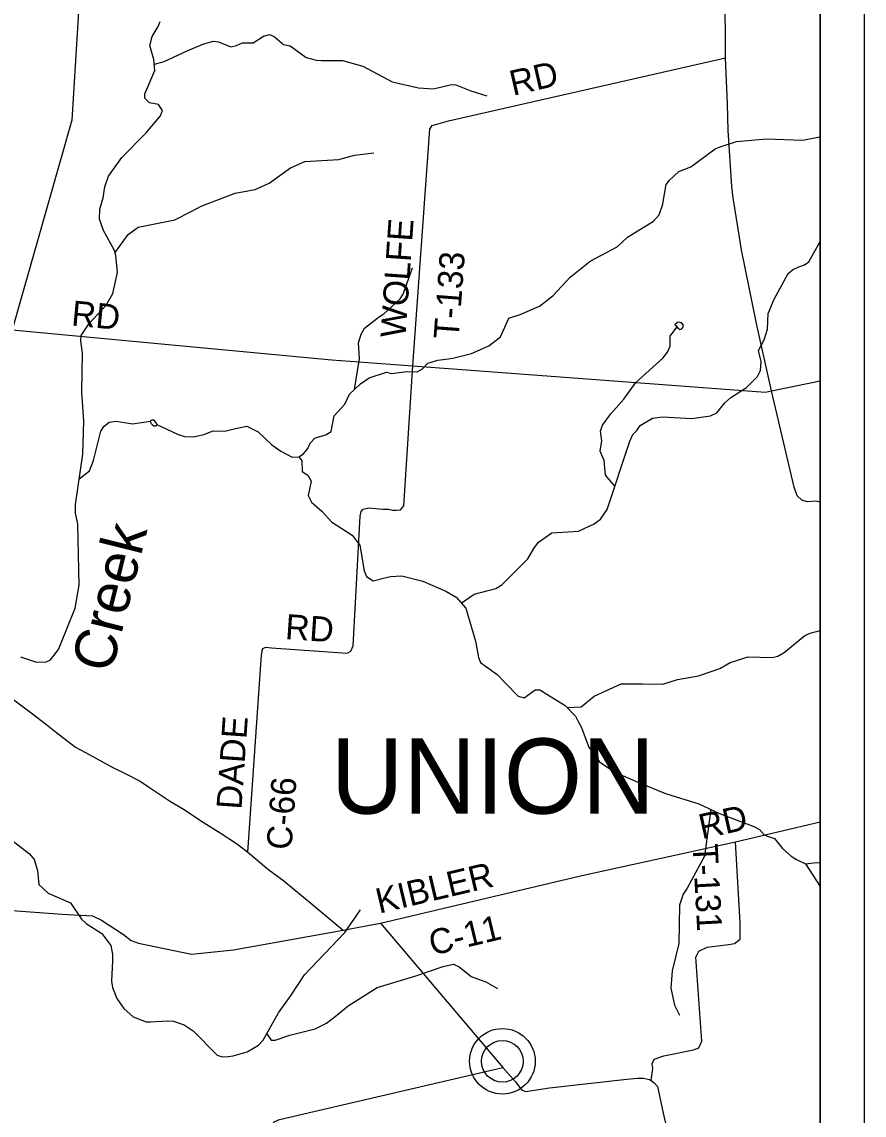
# Model space of a CAD drawing. Extents: x 0 to 48.6, y 0 to 22.
# Drawn here: x 7.09 to 9, y 14.998 to 17.478 of the extents above; entities that cross this region are included whole.
import ezdxf

# ---------------------------------------------------------------- set-up
doc = ezdxf.new("R2010")
doc.units = 0
for name, color, linetype in [('GM_X_Corporation', 7, 'Continuous'), ('GM_X_County_Road', 7, 'Continuous'), ('GM_X_County_Road_Text', 7, 'Continuous'), ('GM_X_County_Text', 7, 'Continuous'), ('GM_X_Minor_Lake', 7, 'Continuous'), ('GM_X_Minor_River', 7, 'Continuous'), ('GM_X_Minor_River_Text', 7, 'Continuous'), ('GM_X_State_Route', 7, 'Continuous'), ('GM_X_Township_Road', 7, 'Continuous'), ('GM_X_Township_Road_Text', 7, 'Continuous'), ('GM_X_Township_Text', 7, 'Continuous'), ('GM_X_Unincorporated', 7, 'Continuous'), ('GM_X_Unincorporated_Location', 7, 'Continuous'), ('SH_Data', 7, 'Continuous')]:
    doc.layers.add(name, color=color, linetype=linetype)

msp = doc.modelspace()

# ---------------------------------------------------------------- linework, layer by layer
at = {"layer": 'GM_X_Corporation'}
msp.add_lwpolyline([(5.0944, 14.1), (8.9, 14.1), (8.9, 19.5692), (8.5348, 19.2897), (7.2261, 18.2847), (6.9471, 18.0777), (6.5365, 17.7727), (5.8387, 17.2541), (5.5264, 17.0064), (4.6225, 16.3345), (4.044, 15.9033), (4.0346, 15.8959), (4.0398, 15.887), (4.3544, 15.3539), (4.4679, 15.1616), (4.7542, 14.6766)], close=True, dxfattribs=at)
at = {"layer": 'GM_X_County_Road'}
msp.add_line((8.7903, 16.6409), (8.9, 16.664), dxfattribs=at)
for points in [[(8.7903, 16.6409), (8.756, 16.7936), (8.7217, 16.9604), (8.7133, 17.013), (8.7028, 17.0786), (8.6997, 17.1041), (8.6913, 17.2315), (8.6903, 17.2915), (8.6855, 17.3963), (8.6851, 17.5535), (8.6814, 17.7601)], [(7.0193, 17.5612), (7.1388, 17.5717), (7.1722, 17.5746), (7.1927, 17.5752), (7.2079, 17.5751), (7.2192, 17.5729), (7.2224, 17.563), (7.2032, 17.2545), (7.0677, 16.7791)], [(6.9605, 15.9949), (6.9706, 16.0404), (6.9818, 16.3461), (6.9871, 16.4731), (6.9936, 16.5052), (7.0677, 16.7791), (7.7928, 16.7109), (7.9765, 16.6977), (8.7761, 16.6379), (8.7903, 16.6409)], [(7.6023, 15.5947), (7.6318, 16.0202), (7.6335, 16.0403), (7.634, 16.046), (7.6349, 16.0513), (7.6366, 16.0565), (7.6431, 16.0598), (7.6563, 16.0583), (7.8279, 16.0458), (7.836, 16.0505), (7.8409, 16.0629), (7.8574, 16.357), (7.8596, 16.3672), (7.8639, 16.3728), (7.8757, 16.3759), (7.9083, 16.3727), (7.9212, 16.3724), (7.9314, 16.3706), (7.9397, 16.37), (7.9488, 16.3713), (7.9559, 16.3798), (7.9765, 16.6977)], [(8.9, 16.3883), (8.8914, 16.3908), (8.8709, 16.3894), (8.8588, 16.3931), (8.8481, 16.4029), (8.841, 16.4228), (8.7903, 16.6409)], [(7.9035, 15.4333), (8.357, 15.5406), (8.7081, 15.6183), (8.9, 15.6634)], [(6.7885, 15.4828), (7.1812, 15.4537), (7.2502, 15.4504), (7.2704, 15.4404), (7.32, 15.4076), (7.3378, 15.3942), (7.3544, 15.388), (7.4748, 15.3636), (7.5699, 15.3732), (7.8187, 15.418)], [(7.8187, 15.418), (7.8658, 15.4267), (7.9035, 15.4333)]]:
    msp.add_lwpolyline(points, dxfattribs=at)
at = {"layer": 'GM_X_Minor_Lake'}
for points in [[(8.5765, 16.7846), (8.5817, 16.7804), (8.5863, 16.7818), (8.589, 16.7845), (8.5902, 16.7901), (8.5861, 16.7955), (8.5804, 16.7967), (8.577, 16.7956), (8.5705, 16.7908)], [(8.5705, 16.7908), (8.5729, 16.7889), (8.5765, 16.7846)], [(7.3964, 16.5645), (7.3953, 16.5679), (7.3912, 16.5725), (7.3882, 16.5744), (7.3856, 16.5745), (7.3825, 16.5734), (7.381, 16.5715), (7.3832, 16.5669), (7.3851, 16.5643), (7.3888, 16.5619), (7.3941, 16.5615)], [(7.3941, 16.5615), (7.3964, 16.5645)]]:
    msp.add_lwpolyline(points, dxfattribs=at)
at = {"layer": 'GM_X_Minor_River'}
for points in [[(7.0866, 16.0375), (7.1232, 16.0256), (7.1452, 16.0264), (7.1548, 16.0312), (7.1726, 16.054), (7.2109, 16.1482), (7.2197, 16.2001), (7.2165, 16.3389), (7.2112, 16.3633), (7.2112, 16.3834), (7.2285, 16.4973), (7.2305, 16.572), (7.2262, 16.638), (7.2272, 16.7264), (7.2235, 16.7541), (7.2244, 16.7666), (7.2423, 16.794), (7.2809, 16.8355), (7.2965, 16.8615), (7.3067, 16.9095), (7.3032, 16.9482), (7.2999, 16.9593), (7.2752, 17.0048), (7.2658, 17.03), (7.2669, 17.0527), (7.2745, 17.0788), (7.2779, 17.1034), (7.2867, 17.1275), (7.3169, 17.1699), (7.372, 17.2259), (7.4045, 17.2649), (7.4088, 17.2769), (7.3999, 17.2903), (7.3791, 17.2941), (7.3691, 17.3045), (7.3688, 17.3143), (7.3917, 17.3671), (7.3894, 17.3921), (7.3801, 17.4245), (7.3857, 17.4445), (7.3986, 17.4675), (7.4033, 17.4784)], [(7.3904, 17.3818), (7.4129, 17.3876), (7.466, 17.413), (7.5022, 17.4283), (7.5243, 17.4337), (7.5357, 17.4327), (7.5635, 17.4213), (7.5769, 17.4241), (7.5906, 17.43), (7.6145, 17.43), (7.6379, 17.4455), (7.6512, 17.4491), (7.6621, 17.4444), (7.6831, 17.4266), (7.6986, 17.4234), (7.7349, 17.397), (7.7576, 17.391), (7.7693, 17.3904), (7.8167, 17.39), (7.8631, 17.3776), (7.9297, 17.3416), (7.989, 17.3282), (8.0235, 17.3261), (8.0642, 17.3357), (8.074, 17.3352), (8.1083, 17.3214), (8.1442, 17.3098)], [(7.3963, 16.5648), (7.4431, 16.5425), (7.4589, 16.5373), (7.479, 16.5366), (7.5026, 16.5416), (7.5236, 16.55), (7.5505, 16.5492), (7.5741, 16.5552), (7.6, 16.5605), (7.6256, 16.5476), (7.6566, 16.5187), (7.6768, 16.5039), (7.7032, 16.4906), (7.718, 16.4915), (7.7283, 16.4978), (7.7383, 16.5098), (7.7438, 16.5222), (7.755, 16.5346), (7.779, 16.541), (7.7913, 16.5488), (7.7983, 16.5844), (7.8222, 16.6109), (7.8328, 16.6331), (7.8575, 16.657), (7.8774, 16.6704), (7.9166, 16.683), (7.9291, 16.6805), (7.9622, 16.685), (7.986, 16.6842), (7.9987, 16.6912), (8.0106, 16.7036), (8.0335, 16.7104), (8.0574, 16.7134), (8.0669, 16.7148), (8.1099, 16.7255), (8.1489, 16.7431), (8.175, 16.7636), (8.1942, 16.8054), (8.2198, 16.8137), (8.264, 16.8327), (8.2944, 16.8573), (8.3333, 16.8988), (8.379, 16.9349), (8.4398, 16.9677), (8.4633, 16.9897), (8.5226, 17.0259), (8.535, 17.0398), (8.5433, 17.0643), (8.545, 17.0745), (8.5512, 17.1086), (8.5586, 17.1191), (8.5798, 17.1385), (8.6072, 17.1487), (8.6621, 17.1899), (8.6732, 17.1947), (8.7109, 17.2066), (8.7785, 17.2128), (8.8599, 17.2092), (8.9, 17.2173)], [(7.3013, 16.9544), (7.3308, 16.9956), (7.3538, 17.0119), (7.4371, 17.0284), (7.4754, 17.0483), (7.4968, 17.0601), (7.5735, 17.0889), (7.6187, 17.0977), (7.6504, 17.1123), (7.6991, 17.1465), (7.7319, 17.1611), (7.8086, 17.1653), (7.8193, 17.1689), (7.8444, 17.1757), (7.8881, 17.1811)], [(8.0863, 16.1597), (8.1157, 16.18), (8.1648, 16.1925), (8.1782, 16.2007), (8.2372, 16.2601), (8.2512, 16.2834), (8.2617, 16.298), (8.2916, 16.3188), (8.3523, 16.3228), (8.3874, 16.3393), (8.402, 16.3497), (8.4171, 16.3718), (8.4685, 16.5269), (8.4756, 16.5416), (8.4844, 16.5513), (8.4918, 16.5626), (8.5198, 16.5788), (8.5429, 16.5823), (8.6096, 16.5782), (8.6514, 16.584), (8.6663, 16.591), (8.6841, 16.6138), (8.6979, 16.6261), (8.7332, 16.6487), (8.7582, 16.6737), (8.7653, 16.6873), (8.7663, 16.7074), (8.7607, 16.7325), (8.7736, 16.7569), (8.7811, 16.7807), (8.7825, 16.8167), (8.7959, 16.8491), (8.8275, 16.9071), (8.8375, 16.9156), (8.8516, 16.9219), (8.865, 16.927), (8.8746, 16.9336), (8.9, 16.9799)], [(7.8444, 16.6443), (7.8553, 16.7143), (7.8532, 16.7496), (7.8592, 16.7696), (7.867, 16.7828), (7.9008, 16.8096), (7.9108, 16.8155), (7.9477, 16.8498), (7.9547, 16.8603), (7.9754, 16.9199)], [(8.4346, 16.4246), (8.4138, 16.45), (8.4106, 16.483), (8.4014, 16.504), (8.4048, 16.5279), (8.4021, 16.5495), (8.4069, 16.5627), (8.4259, 16.589), (8.4552, 16.6223), (8.4824, 16.6598), (8.5435, 16.7154), (8.5543, 16.7285), (8.5599, 16.742), (8.5602, 16.7652), (8.5756, 16.7856)], [(7.22, 16.4412), (7.2431, 16.4595), (7.2526, 16.4829), (7.2688, 16.5494), (7.2758, 16.5603), (7.2881, 16.5699), (7.304, 16.572), (7.3411, 16.5661), (7.3815, 16.5721)], [(7.718, 16.4915), (7.725, 16.482), (7.7254, 16.4581), (7.7381, 16.4499), (7.7459, 16.4361), (7.7393, 16.4032), (7.7467, 16.3883), (7.771, 16.3675), (7.7926, 16.3432), (7.8023, 16.337), (7.8391, 16.3137), (7.8566, 16.2906), (7.8663, 16.2325), (7.8718, 16.2195), (7.8864, 16.2098), (7.9157, 16.2173), (7.9256, 16.2198), (7.9514, 16.2217), (7.9994, 16.2091), (8.051, 16.1867), (8.075, 16.1727), (8.0966, 16.1477), (8.1186, 16.0734), (8.1252, 16.0358), (8.1303, 16.0247), (8.1678, 15.9979), (8.1864, 15.9779), (8.2156, 15.9483), (8.2288, 15.9443), (8.2541, 15.9628), (8.2643, 15.9627), (8.3221, 15.9272), (8.3453, 15.903), (8.3523, 15.8892), (8.3582, 15.8789), (8.3756, 15.8327), (8.3997, 15.7994), (8.435, 15.7757), (8.487, 15.7533), (8.5499, 15.728), (8.625, 15.7045), (8.672, 15.6825), (8.7501, 15.6532), (8.7628, 15.6462), (8.774, 15.6331), (8.797, 15.6259), (8.8148, 15.6029), (8.8347, 15.5852), (8.8467, 15.5778), (8.867, 15.5683), (8.9, 15.5168)], [(8.3265, 15.9226), (8.3585, 15.9244), (8.3881, 15.9482), (8.4492, 15.9765), (8.4977, 15.9761), (8.5432, 15.9758), (8.5771, 15.9863), (8.6246, 15.9946), (8.6727, 16.0113), (8.6964, 16.025), (8.7368, 16.038), (8.7914, 16.0364), (8.8043, 16.0389), (8.8185, 16.0474), (8.8653, 16.0861), (8.8775, 16.0912), (8.9, 16.0974)], [(8.6521, 15.6918), (8.6379, 15.5859), (8.5984, 15.513), (8.5899, 15.4994), (8.5815, 15.4742), (8.5794, 15.3877), (8.5644, 15.3254), (8.5615, 15.286), (8.5696, 15.2479), (8.581, 15.2246)], [(7.0544, 15.6315), (7.1069, 15.5912), (7.1177, 15.5778), (7.1256, 15.553), (7.1285, 15.5214), (7.1498, 15.5018), (7.1999, 15.4794), (7.2251, 15.4426), (7.2356, 15.4325), (7.2712, 15.4104), (7.2913, 15.3827), (7.2955, 15.363), (7.2957, 15.3485), (7.293, 15.3019), (7.2951, 15.2879), (7.3049, 15.2627), (7.3209, 15.2404), (7.3422, 15.2208), (7.372, 15.2097), (7.3818, 15.2095), (7.4198, 15.2123), (7.4338, 15.211), (7.4579, 15.203), (7.4786, 15.1894), (7.533, 15.134), (7.5444, 15.1307), (7.5577, 15.1313), (7.5687, 15.133), (7.6007, 15.142), (7.6267, 15.1571), (7.6371, 15.1684), (7.6718, 15.2304), (7.7009, 15.2702), (7.7305, 15.3167), (7.8226, 15.4128), (7.8494, 15.4514), (7.8575, 15.4642)], [(8.8673, 15.5678), (8.8913, 15.5714), (8.9, 15.5705)], [(7.6451, 15.1826), (7.6549, 15.1685), (7.6644, 15.1679), (7.6972, 15.1796), (7.7554, 15.1942), (7.7807, 15.2071), (7.8002, 15.222), (7.8302, 15.2461), (7.8957, 15.288), (7.9807, 15.3136), (8.0455, 15.3353), (8.0687, 15.3403), (8.0819, 15.3348), (8.1088, 15.3123), (8.1424, 15.3004), (8.1683, 15.2852)]]:
    msp.add_lwpolyline(points, dxfattribs=at)
at = {"layer": 'GM_X_State_Route'}
for points in [[(6.9605, 15.9949), (6.9886, 15.989), (7.0041, 15.9858), (7.0166, 15.9804), (7.0839, 15.9313), (7.1108, 15.9106)], [(7.1108, 15.9106), (7.1462, 15.8834), (7.1655, 15.8684), (7.1915, 15.8477), (7.2116, 15.8331), (7.2339, 15.8208), (7.2963, 15.7865), (7.3274, 15.7719), (7.358, 15.7557), (7.3773, 15.743), (7.4249, 15.7107), (7.4567, 15.6923), (7.5032, 15.6615), (7.5399, 15.6388), (7.5769, 15.6143), (7.6023, 15.5947), (7.6502, 15.5545), (7.6839, 15.5299), (7.7499, 15.4751), (7.8187, 15.418)], [(7.8187, 15.418), (7.8658, 15.4267), (7.9035, 15.4333)], [(7.9035, 15.4333), (8.1804, 15.1061), (8.209, 15.0736), (8.2192, 15.0606), (8.2248, 15.0545), (8.2324, 15.0517), (8.2864, 15.0601), (8.4616, 15.0797), (8.4859, 15.0818), (8.5, 15.0824), (8.5129, 15.0789), (8.5167, 15.0764), (8.5242, 15.0716), (8.5317, 15.0632), (8.5439, 15.0024), (8.559, 14.9377)]]:
    msp.add_lwpolyline(points, dxfattribs=at)
at = {"layer": 'GM_X_Township_Road'}
for points in [[(7.9765, 16.6977), (8.0153, 17.2342), (8.0205, 17.2428), (8.0572, 17.2535), (8.6855, 17.3963)], [(8.5167, 15.0764), (8.521, 15.1038), (8.5196, 15.1149), (8.5242, 15.1255), (8.5459, 15.1329), (8.6128, 15.1465), (8.625, 15.151), (8.6323, 15.1657), (8.6184, 15.3565), (8.625, 15.3702), (8.644, 15.3788), (8.6923, 15.3853), (8.706, 15.3875), (8.719, 15.3976), (8.7188, 15.4345), (8.7081, 15.6183)], [(7.0398, 14.1), (7.0477, 14.1622), (7.268, 14.6779), (7.2906, 14.9021), (7.2983, 14.9038), (7.6625, 14.8205), (7.6772, 14.8167), (7.6879, 14.8187), (7.6911, 14.8254), (7.6578, 14.9749), (7.6622, 14.9831), (7.6738, 14.9885), (8.1804, 15.1061)]]:
    msp.add_lwpolyline(points, dxfattribs=at)
at = {"layer": 'GM_X_Unincorporated'}
for radius in [0.0744, 0.0472]:
    msp.add_circle((8.1796, 15.1203), radius, dxfattribs=at)
at = {"layer": 'GM_X_Unincorporated_Location'}
msp.add_line((8.1796, 15.1203), (8.1796, 15.1203), dxfattribs=at)
at = {"layer": 'SH_Data'}
for p, q in [((9, 21), (9, 14)), ((8.9, 20.9), (8.9, 14.1))]:
    msp.add_line(p, q, dxfattribs=at)

# ---------------------------------------------------------------- texts
at = {"layer": 'GM_X_County_Road_Text'}
for s, rotation, p in [('RD', 354.5354, (7.2006, 16.7894)), ('RD', 356.0551, (7.6858, 16.0781)), ('DADE', 86.0205, (7.5878, 15.6905)), ('C-66', 85.8656, (7.7012, 15.5986)), ('RD', 12.737, (8.6323, 15.6235)), ('KIBLER', 13.2952, (7.9002, 15.4551)), ('C-11', 13.4563, (8.0207, 15.3597))]:
    msp.add_text(s, height=0.05682, rotation=rotation, dxfattribs=at).set_placement(p)
at = {"layer": 'GM_X_County_Text'}
msp.add_text('CLINTON COUNTY', height=0.189394, rotation=36.7754, dxfattribs=at).set_placement((5.6985, 17.3231))
at = {"layer": 'GM_X_Minor_River_Text'}
msp.add_text('Creek', height=0.0947, rotation=75.9834, dxfattribs=at).set_placement((7.2931, 15.9983))
at = {"layer": 'GM_X_Township_Road_Text'}
for s, rotation, p in [('RD', 12.9561, (8.2035, 17.31)), ('WOLFE', 86.0001, (7.9596, 16.7598)), ('T-133', 85.7741, (8.0802, 16.7568)), ('T-131', 273.0864, (8.6109, 15.6121))]:
    msp.add_text(s, height=0.05682, rotation=rotation, dxfattribs=at).set_placement(p)
at = {"layer": 'GM_X_Township_Text'}
msp.add_text('UNION', height=0.17045, rotation=0, dxfattribs=at).set_placement((7.7906, 15.682))

doc.saveas('drawing.dxf')
